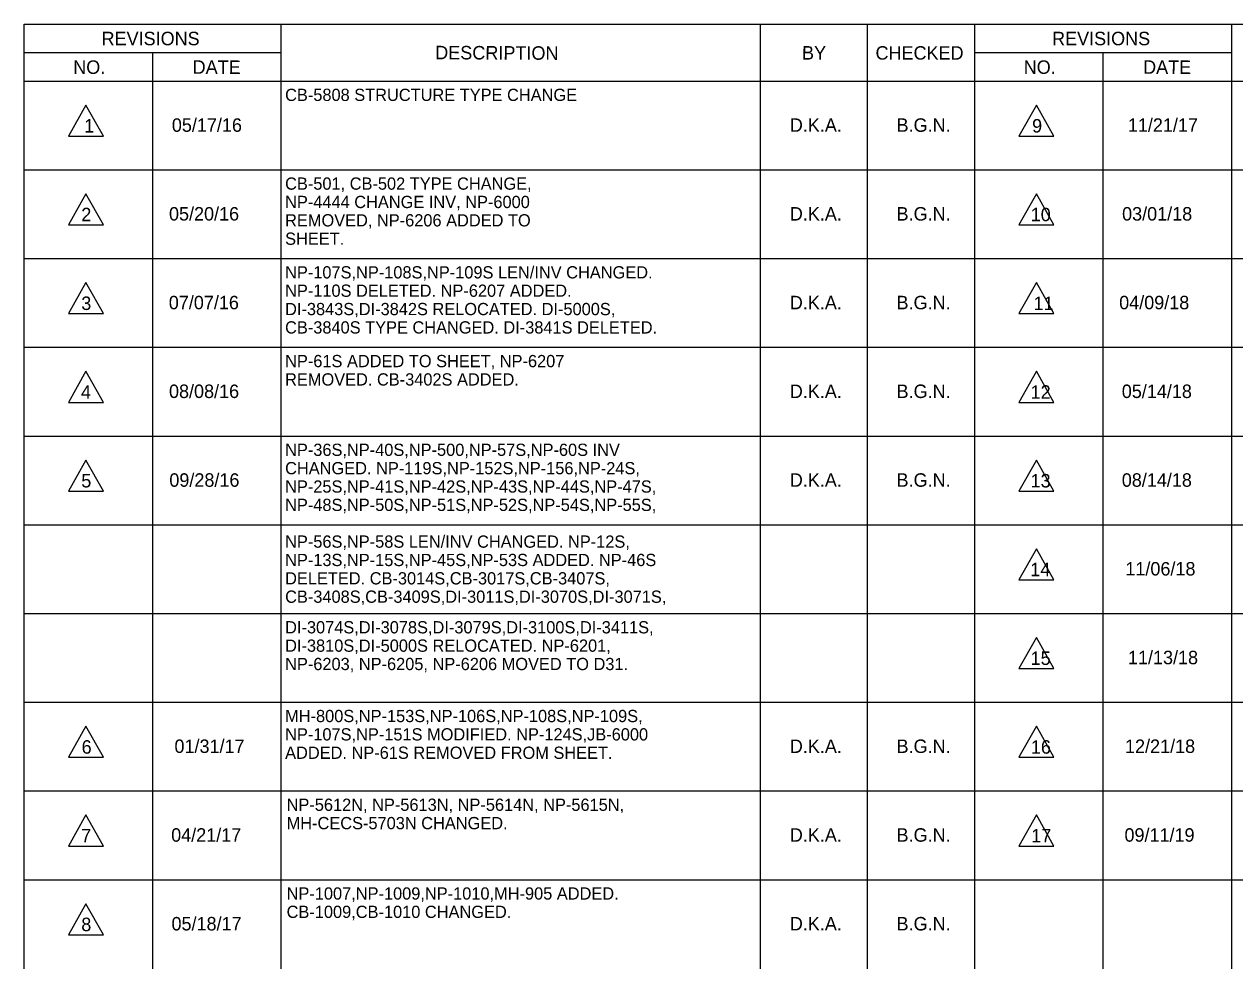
# Model space of a CAD drawing. Extents: x 261099 to 262774, y 322332 to 323393.
# Drawn here: x 261944 to 262339.6, y 322331.9 to 322640.6 of the extents above; entities that cross this region are included whole.
import ezdxf

# ---------------------------------------------------------------- set-up
doc = ezdxf.new("R2010")
doc.units = 0
doc.layers.add('RD_SHT_TX', color=7, linetype='Continuous')

msp = doc.modelspace()

# ---------------------------------------------------------------- linework, layer by layer
at = {"layer": 'RD_SHT_TX'}
for p, q in [((261944.02, 322331.93), (261944.02, 322640.63)), ((261944.02, 322640.63), (262254.62, 322640.63)), ((262028.02, 322331.93), (262028.02, 322640.63)), ((262184.62, 322331.93), (262184.62, 322640.63)), ((262219.62, 322331.93), (262219.62, 322640.63)), ((262254.62, 322331.93), (262254.62, 322640.63)), ((262254.62, 322640.63), (262565.22, 322640.63)), ((262338.62, 322331.93), (262338.62, 322640.63)), ((262028.02, 322631.28), (261944.02, 322631.28)), ((261986.02, 322331.93), (261986.02, 322631.28)), ((262338.62, 322631.28), (262254.62, 322631.28)), ((262296.62, 322331.93), (262296.62, 322631.28)), ((262565.22, 322621.93), (261944.02, 322621.93)), ((261964.18, 322614.19), (261958.49, 322604.05)), ((261969.88, 322604.05), (261964.18, 322614.19)), ((262274.78, 322614.19), (262269.09, 322604.05)), ((262280.48, 322604.05), (262274.78, 322614.19)), ((261958.49, 322604.05), (261969.88, 322604.05)), ((262269.09, 322604.05), (262280.48, 322604.05)), ((262565.22, 322592.93), (261944.02, 322592.93)), ((262565.22, 322592.93), (261944.02, 322592.93)), ((261964.18, 322585.19), (261958.49, 322575.05)), ((261969.88, 322575.05), (261964.18, 322585.19)), ((262274.78, 322585.19), (262269.09, 322575.05)), ((262280.48, 322575.05), (262274.78, 322585.19)), ((261958.49, 322575.05), (261969.88, 322575.05)), ((262269.09, 322575.05), (262280.48, 322575.05)), ((262565.22, 322563.93), (261944.02, 322563.93)), ((261964.18, 322556.19), (261958.49, 322546.05)), ((261969.88, 322546.05), (261964.18, 322556.19)), ((262274.78, 322556.19), (262269.09, 322546.05)), ((262280.48, 322546.05), (262274.78, 322556.19)), ((261958.49, 322546.05), (261969.88, 322546.05)), ((262269.09, 322546.05), (262280.48, 322546.05)), ((262565.22, 322534.93), (261944.02, 322534.93)), ((261964.18, 322527.19), (261958.49, 322517.05)), ((261969.88, 322517.05), (261964.18, 322527.19)), ((262274.78, 322527.19), (262269.09, 322517.05)), ((262280.48, 322517.05), (262274.78, 322527.19)), ((261958.49, 322517.05), (261969.88, 322517.05)), ((262269.09, 322517.05), (262280.48, 322517.05)), ((262565.22, 322505.93), (261944.02, 322505.93)), ((261964.18, 322498.19), (261958.49, 322488.05)), ((261969.88, 322488.05), (261964.18, 322498.19)), ((262274.78, 322498.19), (262269.09, 322488.05)), ((262280.48, 322488.05), (262274.78, 322498.19)), ((261958.49, 322488.05), (261969.88, 322488.05)), ((262269.09, 322488.05), (262280.48, 322488.05)), ((262565.22, 322476.93), (261944.02, 322476.93)), ((262274.78, 322469.19), (262269.09, 322459.05)), ((262280.48, 322459.05), (262274.78, 322469.19)), ((262269.09, 322459.05), (262280.48, 322459.05)), ((262565.22, 322447.93), (261944.02, 322447.93)), ((262274.78, 322440.19), (262269.09, 322430.05)), ((262280.48, 322430.05), (262274.78, 322440.19)), ((262269.09, 322430.05), (262280.48, 322430.05)), ((262565.22, 322418.93), (261944.02, 322418.93)), ((261964.19, 322411.19), (261958.49, 322401.05)), ((261969.88, 322401.05), (261964.19, 322411.19)), ((262274.78, 322411.19), (262269.09, 322401.05)), ((262280.48, 322401.05), (262274.78, 322411.19)), ((261958.49, 322401.05), (261969.88, 322401.05)), ((262269.09, 322401.05), (262280.48, 322401.05)), ((262565.22, 322389.93), (261944.02, 322389.93)), ((261964.18, 322382.19), (261958.49, 322372.05)), ((261969.88, 322372.05), (261964.18, 322382.19)), ((262274.78, 322382.19), (262269.09, 322372.05)), ((262280.48, 322372.05), (262274.78, 322382.19)), ((261958.49, 322372.05), (261969.88, 322372.05)), ((262269.09, 322372.05), (262280.48, 322372.05)), ((262565.22, 322360.93), (261944.02, 322360.93)), ((261964.18, 322353.19), (261958.49, 322343.05)), ((261969.88, 322343.05), (261964.18, 322353.19)), ((261958.49, 322343.05), (261969.88, 322343.05))]:
    msp.add_line(p, q, dxfattribs=at)

# ---------------------------------------------------------------- texts
for s, p in [('REVISIONS', (261969.31, 322633.75)), ('REVISIONS', (262279.91, 322633.75)), ('CHECKED', (262222.22, 322629.05)), ('NO.', (261960.04, 322624.4)), ('NO.', (262270.64, 322624.4)), ('1', (261963.65, 322605.23)), ('9', (262273.38, 322605.23)), ('2', (261962.68, 322576.23)), ('10', (262272.93, 322576.23)), ('3', (261962.68, 322547.23)), ('11', (262273.87, 322547.23)), ('4', (261962.57, 322518.23)), ('12', (262272.9, 322518.23)), ('5', (261962.68, 322489.23)), ('13', (262272.9, 322489.23)), ('14', (262272.79, 322460.23)), ('15', (262272.9, 322431.23)), ('6', (261962.79, 322402.23)), ('16', (262273, 322402.23)), ('7', (261962.64, 322373.23)), ('17', (262273.11, 322373.23)), ('8', (261962.68, 322344.23))]:
    msp.add_text(s, height=4.4, dxfattribs=at).set_placement(p)
for s, height, rotation, p in [('DESCRIPTION', 4.4083, 359.7246, (262078.32, 322629.17)), ('BY', 4.408, 359.7246, (262198.18, 322629.09)), ('DATE', 4.408, 359.7246, (261999.05, 322624.43)), ('DATE', 4.408, 359.7246, (262309.65, 322624.43)), ('CB-5808 STRUCTURE TYPE CHANGE', 4, 360, (262029.28, 322615.54)), ('05/17/16', 4.4, 360, (261992.27, 322605.46)), ('D.K.A.', 4.4, 360, (262194.21, 322605.46)), ('B.G.N.', 4.4, 360, (262229.09, 322605.46)), ('11/21/17', 4.4, 360, (262304.67, 322605.46)), ('CB-501, CB-502 TYPE CHANGE,', 4, 360, (262029.28, 322586.54)), ('NP-4444 CHANGE INV, NP-6000', 4, 360, (262029.28, 322580.54)), ('05/20/16', 4.4, 360, (261991.34, 322576.46)), ('D.K.A.', 4.4, 360, (262194.21, 322576.46)), ('B.G.N.', 4.4, 360, (262229.09, 322576.46)), ('03/01/18', 4.4, 360, (262302.79, 322576.46)), ('REMOVED, NP-6206 ADDED TO', 4, 360, (262029.28, 322574.54)), ('SHEET.', 4, 360, (262029.28, 322568.54)), ('NP-107S,NP-108S,NP-109S LEN/INV CHANGED.', 4, 360, (262029.27, 322557.54)), ('NP-110S DELETED. NP-6207 ADDED. ', 4, 360, (262029.27, 322551.54)), ('07/07/16', 4.4, 360, (261991.27, 322547.46)), ('DI-3843S,DI-3842S RELOCATED. DI-5000S,', 4, 360, (262029.27, 322545.54)), ('D.K.A.', 4.4, 360, (262194.21, 322547.46)), ('B.G.N.', 4.4, 360, (262229.08, 322547.46)), ('04/09/18', 4.4, 360, (262301.84, 322547.46)), ('CB-3840S TYPE CHANGED. DI-3841S DELETED.', 4, 360, (262029.27, 322539.54)), ('NP-61S ADDED TO SHEET, NP-6207', 4, 360, (262029.28, 322528.54)), ('REMOVED. CB-3402S ADDED.', 4, 360, (262029.28, 322522.54)), ('08/08/16', 4.4, 360, (261991.34, 322518.46)), ('D.K.A.', 4.4, 360, (262194.21, 322518.46)), ('B.G.N.', 4.4, 360, (262229.09, 322518.46)), ('05/14/18', 4.4, 360, (262302.69, 322518.46)), ('NP-36S,NP-40S,NP-500,NP-57S,NP-60S INV ', 4, 360, (262029.28, 322499.54)), ('CHANGED. NP-119S,NP-152S,NP-156,NP-24S,', 4, 360, (262029.28, 322493.54)), ('09/28/16', 4.4, 360, (261991.45, 322489.46)), ('D.K.A.', 4.4, 360, (262194.21, 322489.46)), ('B.G.N.', 4.4, 360, (262229.09, 322489.46)), ('08/14/18', 4.4, 360, (262302.69, 322489.46)), ('NP-25S,NP-41S,NP-42S,NP-43S,NP-44S,NP-47S,', 4, 360, (262029.28, 322487.54)), ('NP-48S,NP-50S,NP-51S,NP-52S,NP-54S,NP-55S,', 4, 360, (262029.28, 322481.54)), ('NP-56S,NP-58S LEN/INV CHANGED. NP-12S,', 4, 360, (262029.28, 322469.54)), ('NP-13S,NP-15S,NP-45S,NP-53S ADDED. NP-46S', 4, 360, (262029.28, 322463.54)), ('11/06/18', 4.4, 360, (262303.86, 322460.46)), ('DELETED. CB-3014S,CB-3017S,CB-3407S,', 4, 360, (262029.28, 322457.54)), ('CB-3408S,CB-3409S,DI-3011S,DI-3070S,DI-3071S,', 4, 360, (262029.28, 322451.54)), ('DI-3074S,DI-3078S,DI-3079S,DI-3100S,DI-3411S,', 4, 360, (262029.28, 322441.54)), ('DI-3810S,DI-5000S RELOCATED. NP-6201,', 4, 360, (262029.28, 322435.54)), ('11/13/18', 4.4, 360, (262304.71, 322431.46)), ('NP-6203, NP-6205, NP-6206 MOVED TO D31.', 4, 360, (262029.28, 322429.54)), ('MH-800S,NP-153S,NP-106S,NP-108S,NP-109S,', 4, 360, (262029.28, 322412.54)), ('NP-107S,NP-151S MODIFIED. NP-124S,JB-6000', 4, 360, (262029.28, 322406.54)), ('01/31/17', 4.4, 360, (261993.12, 322402.46)), ('D.K.A.', 4.4, 360, (262194.21, 322402.46)), ('B.G.N.', 4.4, 360, (262229.09, 322402.46)), ('12/21/18', 4.4, 360, (262303.75, 322402.46)), ('ADDED. NP-61S REMOVED FROM SHEET.', 4, 360, (262029.28, 322400.54)), ('NP-5612N, NP-5613N, NP-5614N, NP-5615N,', 4, 360, (262029.77, 322383.54)), ('MH-CECS-5703N CHANGED.', 4, 360, (262029.77, 322377.54)), ('04/21/17', 4.4, 360, (261992.05, 322373.46)), ('D.K.A.', 4.4, 360, (262194.21, 322373.46)), ('B.G.N.', 4.4, 360, (262229.09, 322373.46)), ('09/11/19', 4.4, 360, (262303.57, 322373.46)), ('NP-1007,NP-1009,NP-1010,MH-905 ADDED.', 4, 360, (262029.77, 322354.54)), ('CB-1009,CB-1010 CHANGED.', 4, 360, (262029.77, 322348.54)), ('05/18/17', 4.4, 360, (261992.16, 322344.46)), ('D.K.A.', 4.4, 360, (262194.21, 322344.46)), ('B.G.N.', 4.4, 360, (262229.09, 322344.46))]:
    msp.add_text(s, height=height, rotation=rotation, dxfattribs=at).set_placement(p)

doc.saveas('drawing.dxf')
